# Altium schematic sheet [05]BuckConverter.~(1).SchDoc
size A4; SheetNumber: 3; SheetTotal: 3
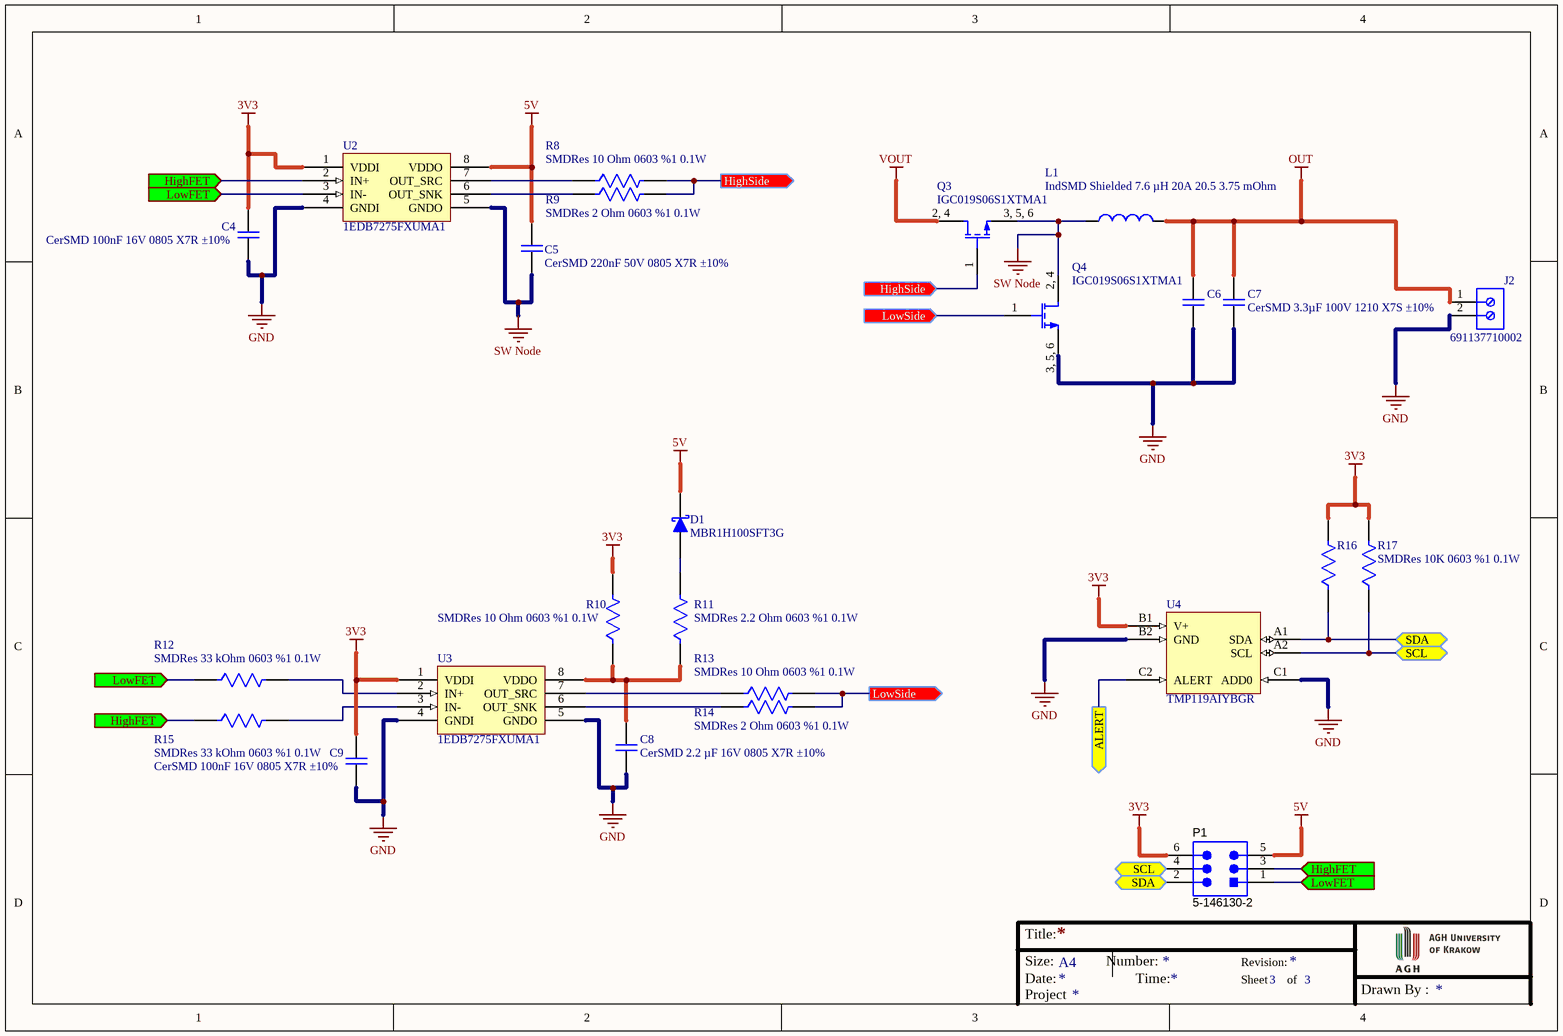
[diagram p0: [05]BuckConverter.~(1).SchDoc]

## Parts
C4  CerSMD 100nF 16V 0805 X7R ±10%  [CAPC2012X09N]
C5  CerSMD 220nF 50V 0805 X7R ±10%  [CAPC2012X09N]
C6  CerSMD 3.3µF 100V 1210 X7S ±10%  [CAPC3225X28N]  (value not drawn)
C7  CerSMD 3.3µF 100V 1210 X7S ±10%  [CAPC3225X28N]
C8  CerSMD 2.2 µF 16V 0805 X7R ±10%  [CAPC2012X09N]
C9  CerSMD 100nF 16V 0805 X7R ±10%  [CAPC2012X09N]
D1  MBR1H100SFT3G  [SODFL360X95-2N]
J2  691137710002  [691137710002]
L1  IndSMD Shielded 7.6 µH 20A 20.5 3.75 mOhm  [7443557760]
P1  5-146130-2  [TECO-5-146130-2_V]
Q3  IGC019S06S1XTMA1  [IGC019S06S1XTMA1]
Q4  IGC019S06S1XTMA1  [IGC019S06S1XTMA1]
R8  SMDRes 10 Ohm 0603 %1 0.1W  [RESC1508X06N]
R9  SMDRes 2 Ohm 0603 %1 0.1W  [RESC1508X06N]
R10  SMDRes 10 Ohm 0603 %1 0.1W  [RESC1508X06N]
R11  SMDRes 2.2 Ohm 0603 %1 0.1W  [RESC1508X06N]
R12  SMDRes 33 kOhm 0603 %1 0.1W  [RESC1508X06N]
R13  SMDRes 10 Ohm 0603 %1 0.1W  [RESC1508X06N]
R14  SMDRes 2 Ohm 0603 %1 0.1W  [RESC1508X06N]
R15  SMDRes 33 kOhm 0603 %1 0.1W  [RESC1508X06N]
R16  SMDRes 10K 0603 %1 0.1W  [RESC1508X06N]  (value not drawn)
R17  SMDRes 10K 0603 %1 0.1W  [RESC1508X06N]
U2  1EDB7275FXUMA1  [SOIC127P600X175-8N]
U3  1EDB7275FXUMA1  [SOIC127P600X175-8N]
U4  TMP119AIYBGR  [BGA6C40P2X3_95X149X52]

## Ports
ALERT (out), HighFET (in, see [05]BuckConverter[1A], [05]BuckConverter[1C]), HighFET (in, see [05]BuckConverter[1A], [05]BuckConverter[4D]), HighFET (in, see [05]BuckConverter[1C], [05]BuckConverter[4D]), HighSide (in, see [05]BuckConverter[2A]), HighSide (out, see [05]BuckConverter[3B]), LowFET (in, see [05]BuckConverter[1A], [05]BuckConverter[1C]), LowFET (in, see [05]BuckConverter[1A], [05]BuckConverter[4D]), LowFET (in, see [05]BuckConverter[1C], [05]BuckConverter[4D]), LowSide (in, see [05]BuckConverter[3C]), LowSide (out, see [05]BuckConverter[3B]), SCL (bidir, see [05]BuckConverter[3D]), SCL (bidir, see [05]BuckConverter[4C]), SDA (bidir, see [05]BuckConverter[3D]), SDA (bidir, see [05]BuckConverter[4C])

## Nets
3V3: C4.1 C9.1 P1.6 R10.2 R16.2 R17.2 U2.1(VDDI) U3.1(VDDI) U4.B1(V+)
5V: C5.1 D1.2(K) P1.5 U2.8(VDDO)
GND: C4.2 C6.2 C7.2 C8.2 C9.2 J2.2 Q4.3,_5,_6(S) U2.4(GNDI) U3.4(GNDI) U3.5(GNDO) U4.B2(GND) U4.C1(ADD0)
OUT: C6.1 C7.1 J2.1 L1.2
SW Node: C5.2 L1.1 Q3.3,_5,_6(S) Q4.2,_4(D) U2.5(GNDO)
VOUT: Q3.2,_4(D)
ALERT: U4.C2(ALERT) ; port ALERT
HighFET: P1.3 R15.1 U2.2(IN+) ; port HighFET
HighSide: Q3.1(G) R8.2 R9.2 ; port HighSide
LowFET: P1.1 R12.1 U2.3(IN-) ; port LowFET
LowSide: Q4.1(G) R13.2 R14.2 ; port LowSide
SCL: P1.4 R17.1 U4.A2(SCL) ; port SCL
SDA: P1.2 R16.1 U4.A1(SDA) ; port SDA
NetC8_1: C8.1 R10.1 R11.1 U3.8(VDDO)
NetD1_1: D1.1(A) R11.2
NetR8_1: R8.1 U2.7(OUT_SRC)
NetR9_1: R9.1 U2.6(OUT_SNK)
NetR12_2: R12.2 U3.2(IN+)
NetR13_1: R13.1 U3.7(OUT_SRC)
NetR14_1: R14.1 U3.6(OUT_SNK)
NetR15_2: R15.2 U3.3(IN-)

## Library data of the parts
C4 C9 = CMP-00013-1: Ceramic Capacitor SMD 100nF 10V 0805 X7R ±10%; Manufacturer Number: 885012207016; Manufacturer: Würth Elektronik
C5 = CMP-00016-1: Ceramic Capacitor SMD 220nF 50V 0805 X7R ±10%; Manufacturer: Murata Electronics; Manufacturer Number: GRM21BR71H224KA01L; Voltage: 10V
C6 C7 = CMP-00010-1: Ceramic Capacitor SMD 3.3µF 100V 1210 X7S ±10%; Manufacturer: Samsung Electro-Mechanics; Manufacturer Number: C3225X7S2A335K200AB; Voltage: 16V; Temperature Coefficient: X7R
C8 = CMP-00014-1: Ceramic Capacitor SMD 2.2 µF 16V 0805 X7R ±10%; Manufacturer Number: C2012X7R1C225K125AB; Manufacturer: TDK Corporation
D1 = CMP-00020-2
J2 = CMP-00022-1: würth terminal
L1 = CMP-00011-1: Inductor SMD Shielded 7.6 µH 20A 20.5 3.75 mOhm
P1 = CMP-002-00018-2: Male Header, Pitch 2.54 mm, 2 x 3 Position, Height 8.13 mm, -65 to 125 degC, RoHS, Tube; Manufacturer: TE Connectivity
Q3 Q4 = CMP-00009-1: GaNFET N-Ch - 60V - 27A (Ta), 99A (Tc); Manufacturer: Infineon Technologies; Vgs(th): 2.9V; Rdson: 1.9mOhm; Drive Voltage: 5V; FET Type: N-Channel; Vgs(max): ±6.5V
R8 R10 R13 = CMP-00017-1: Res Thick Film 0603 10 Ohm Ohm 1% 0.1W(1/10W) ±100ppm/C Pad SMD T/R Automotive AEC-Q200; Manufacturer Number: RMCF0603FT10R0; Manufacturer: Stackpole Electronics Inc
R9 R14 = CMP-00019-1: Res Thick Film 0603 2 Ohm Ohm 1% 0.1W(1/10W) ±100ppm/C Pad SMD T/R Automotive AEC-Q200; Manufacturer: Stackpole Electronics Inc; Manufacturer Number: RMCF0603FT2R00
R11 = CMP-00015-1: Res Thick Film 0603 2.2 Ohm Ohm 1% 0.1W(1/10W) ±100ppm/C Pad SMD T/R Automotive AEC-Q200; Manufacturer Number: RMCF0603FT2R20; Manufacturer: Stackpole Electronics Inc
R12 R15 = CMP-00018-1: Res Thick Film 0603 33 kOhm Ohm 1% 0.1W(1/10W) ±100ppm/C Pad SMD T/R Automotive AEC-Q200; Manufacturer: Stackpole Electronics Inc; Manufacturer Number: RMCF0603FT33K0
R16 R17 = CMP-00001-1-2: Res Thick Film 0603 10K Ohm 1% 0.1W(1/10W) ±100ppm/C Pad SMD T/R Automotive AEC-Q200; Manufacturer Number: RMCF0603FT10K0; Manufacturer: Stackpole Electronics Inc
U2 U3 = CMP-00012-1
U4 = CMP-00021-1: Temperature Sensor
